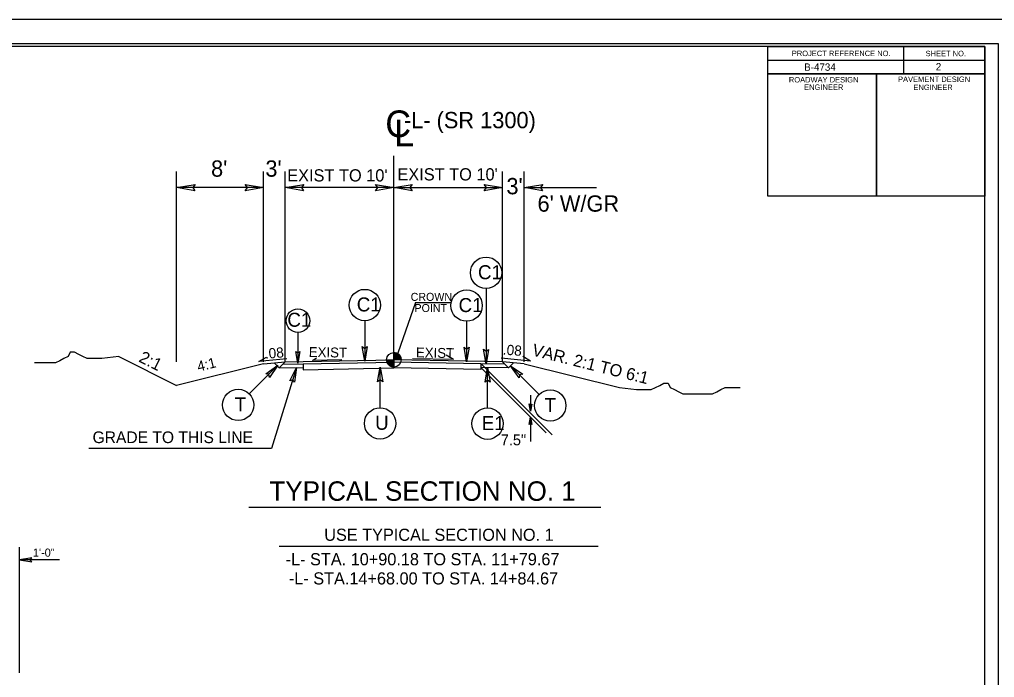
# Model space of a CAD drawing. Extents: x 1818040 to 1825768, y 638918 to 648046.
# Drawn here: x 1821171 to 1822069, y 645878 to 646483 of the extents above; entities that cross this region are included whole.
import ezdxf

# ---------------------------------------------------------------- set-up
doc = ezdxf.new("R2010")
doc.units = 0
for name, color, linetype in [('Default', 7, 'Continuous'), ('Old_Level_1', 7, 'Continuous'), ('Prop Dimension', 7, 'Continuous'), ('Prop Dimension Text', 7, 'Continuous'), ('Sheet Data Field CELL', 7, 'Continuous'), ('Sheet Plot Border Inside CELL', 7, 'Continuous'), ('Sheet Plot Border Outside CELL', 7, 'Continuous'), ('Sheet Typical CELL', 7, 'Continuous'), ('Typical Grade Point Symbol CELL', 7, 'Continuous'), ('Typical ID Circle CELL', 7, 'Continuous'), ('Typical Pavement Slope CELL', 7, 'Continuous'), ('Typical Pavement Slope Information CELL', 7, 'Continuous'), ('Typical Shoulder Slope CELL', 7, 'Continuous'), ('Typical Slope Point Local CELL', 7, 'Continuous'), ('Typical Terminator CELL', 7, 'Continuous'), ('Typical Text Centerline CELL', 7, 'Continuous'), ('Typical Text General CELL', 7, 'Continuous'), ('Typical Text Grade Point CELL', 7, 'Continuous'), ('Typical Text ID Circle CELL', 7, 'Continuous'), ('Typical Text Label CELL', 7, 'Continuous')]:
    doc.layers.add(name, color=color, linetype=linetype)

msp = doc.modelspace()

# ---------------------------------------------------------------- linework, layer by layer
at = {"layer": 'Default'}
for p, q in [((1821440.94, 646169.55), (1821444.36, 646172.12)), ((1821467.78, 646170.19), (1821440.94, 646169.55)), ((1821171.15, 645881.99), (1821171.15, 645997.66)), ((1821207.77, 645986.11), (1821171.15, 645986.11))]:
    msp.add_line(p, q, dxfattribs=at)
at = {"layer": 'Old_Level_1'}
for p, q in [((1821315.74, 646168.26), (1821315.74, 646343.71)), ((1821425.94, 646163.07), (1821403.15, 646088.52)), ((1821410.22, 646162.74), (1821405.54, 646167.41)), ((1821415.74, 646168.26), (1821410.22, 646162.74)), ((1821410.22, 646162.74), (1821432.22, 646163.18)), ((1821413.62, 646166.14), (1821432.22, 646166.51)), ((1821432.22, 646166.51), (1821515.74, 646168.18)), ((1821432.22, 646166.51), (1821432.22, 646161.09)), ((1821432.22, 646161.09), (1821515.74, 646162.76)), ((1821595.7, 646166.58), (1821515.74, 646168.18)), ((1821595.7, 646161.16), (1821515.74, 646162.76)), ((1821617.87, 646166.14), (1821595.7, 646166.58)), ((1821595.7, 646166.58), (1821595.7, 646161.16)), ((1821595.7, 646163.25), (1821655.83, 646103.12)), ((1821621.27, 646162.74), (1821595.7, 646163.25)), ((1821596.25, 646166.25), (1821661.41, 646101.09)), ((1821615.74, 646168.26), (1821621.27, 646162.74)), ((1821621.27, 646162.74), (1821625.95, 646167.41)), ((1821641.47, 646137.69), (1821641.47, 646122.85)), ((1821641.47, 646117.35), (1821641.47, 646095.04)), ((1821403.15, 646088.52), (1821234.74, 646088.52))]:
    msp.add_line(p, q, dxfattribs=at)
at = {"layer": 'Prop Dimension'}
for p, q in [((1821515.74, 646170.26), (1821515.74, 646357.92)), ((1821395.74, 646168.26), (1821395.74, 646343.71)), ((1821415.74, 646168.26), (1821415.74, 646343.71)), ((1821615.74, 646168.26), (1821615.74, 646343.71)), ((1821635.74, 646168.26), (1821635.74, 646343.71)), ((1821395.74, 646328.71), (1821315.74, 646328.71)), ((1821515.74, 646328.71), (1821415.74, 646328.71)), ((1821515.74, 646328.71), (1821615.74, 646328.71)), ((1821635.74, 646328.71), (1821702.28, 646328.71))]:
    msp.add_line(p, q, dxfattribs=at)
at = {"layer": 'Sheet Plot Border Inside CELL'}
msp.add_lwpolyline([(1822072.43, 646461.05), (1820405.93, 646461.05), (1820405.93, 645405.95), (1822072.43, 645405.95)], close=True, dxfattribs=at)
at = {"layer": 'Sheet Plot Border Outside CELL'}
msp.add_lwpolyline([(1822076.93, 646483.5), (1820392.93, 646483.5), (1820392.93, 645383.5), (1822076.93, 645383.5)], close=True, dxfattribs=at)
at = {"layer": 'Sheet Typical CELL'}
for p, q in [((1822076.93, 646483.5), (1820392.93, 646483.5)), ((1821984.93, 646458.45), (1821984.93, 646433.45)), ((1821859.88, 646445.95), (1822059.93, 646445.95)), ((1821959.93, 646433.45), (1821959.93, 646321))]:
    msp.add_line(p, q, dxfattribs=at)
for points in [[(1822059.93, 646458.5), (1820559.93, 646458.5), (1820559.93, 645408.5), (1822059.93, 645408.5)], [(1821859.88, 646458.5), (1822059.93, 646458.5), (1822059.93, 646433.45), (1821859.88, 646433.45)], [(1821859.88, 646433.45), (1821959.93, 646433.45), (1821959.93, 646320.95), (1821859.88, 646320.95)], [(1821959.93, 646433.45), (1822059.93, 646433.45), (1822059.93, 646320.95), (1821959.93, 646320.95)]]:
    msp.add_lwpolyline(points, close=True, dxfattribs=at)
at = {"layer": 'Typical Grade Point Symbol CELL'}
for p, q in [((1821515.74, 646170.26), (1821515.74, 646176.98)), ((1821509.03, 646170.26), (1821515.74, 646170.26)), ((1821515.73, 646163.55), (1821515.74, 646170.26)), ((1821515.74, 646170.26), (1821515.73, 646163.55)), ((1821522.46, 646170.26), (1821515.74, 646170.26))]:
    msp.add_line(p, q, dxfattribs=at)
for points in [[(1821515.8, 646176.98), (1821515.8, 646176.98), (1821515.8, 646170.26)], [(1821515.94, 646176.98), (1821515.94, 646170.26)], [(1821516.07, 646176.96), (1821516.07, 646170.26)], [(1821516.21, 646176.96), (1821516.21, 646170.26)], [(1821516.34, 646176.95), (1821516.34, 646170.26)], [(1821516.48, 646176.93), (1821516.48, 646170.26)], [(1821516.61, 646176.92), (1821516.61, 646170.26)], [(1821516.74, 646176.9), (1821516.74, 646170.26)], [(1821516.88, 646176.89), (1821516.88, 646170.26)], [(1821517.01, 646176.86), (1821517.01, 646170.26)], [(1821517.15, 646176.83), (1821517.15, 646170.26)], [(1821517.28, 646176.8), (1821517.28, 646170.26)], [(1821517.42, 646176.77), (1821517.42, 646170.26)], [(1821517.55, 646176.73), (1821517.55, 646170.26)], [(1821517.68, 646176.69), (1821517.68, 646170.26)], [(1821517.82, 646176.65), (1821517.82, 646170.26)], [(1821517.95, 646176.61), (1821517.95, 646170.26)], [(1821518.09, 646176.56), (1821518.09, 646170.26)], [(1821518.22, 646176.5), (1821518.22, 646170.26)], [(1821518.36, 646176.44), (1821518.36, 646170.26)], [(1821518.49, 646176.38), (1821518.49, 646170.26)], [(1821518.62, 646176.32), (1821518.62, 646170.26)], [(1821518.76, 646176.26), (1821518.76, 646170.26)], [(1821518.89, 646176.19), (1821518.89, 646170.26)], [(1821519.03, 646176.11), (1821519.03, 646170.26)], [(1821519.16, 646176.04), (1821519.16, 646170.26)], [(1821519.3, 646175.96), (1821519.3, 646170.26)], [(1821519.43, 646175.87), (1821519.43, 646170.26)], [(1821519.56, 646175.78), (1821519.56, 646170.26)], [(1821519.7, 646175.68), (1821519.7, 646170.26)], [(1821519.83, 646175.59), (1821519.83, 646170.26)], [(1821519.97, 646175.49), (1821519.97, 646170.26)], [(1821520.1, 646175.37), (1821520.1, 646170.26)], [(1821520.23, 646175.25), (1821520.23, 646170.26)], [(1821520.37, 646175.13), (1821520.37, 646170.26)], [(1821520.5, 646174.99), (1821520.5, 646170.26)], [(1821520.64, 646174.86), (1821520.64, 646170.26)], [(1821520.77, 646174.71), (1821520.77, 646170.26)], [(1821520.91, 646174.55), (1821520.91, 646170.26)], [(1821521.04, 646174.38), (1821521.04, 646170.26)], [(1821521.18, 646174.2), (1821521.18, 646170.26)], [(1821521.31, 646174.01), (1821521.31, 646170.26)], [(1821521.44, 646173.8), (1821521.44, 646170.26)], [(1821521.58, 646173.58), (1821521.58, 646170.26)], [(1821521.71, 646173.34), (1821521.71, 646170.26)], [(1821521.85, 646173.05), (1821521.85, 646170.26)], [(1821521.98, 646172.74), (1821521.98, 646170.26)], [(1821522.11, 646172.37), (1821522.11, 646170.26)], [(1821522.25, 646171.91), (1821522.25, 646170.26)], [(1821522.38, 646171.22), (1821522.38, 646170.26)], [(1821509.06, 646170.26), (1821509.06, 646169.53)], [(1821509.19, 646170.26), (1821509.19, 646168.74)], [(1821509.33, 646170.26), (1821509.33, 646168.27)], [(1821509.46, 646170.26), (1821509.46, 646167.86)], [(1821509.6, 646170.26), (1821509.6, 646167.55)], [(1821509.73, 646170.26), (1821509.73, 646167.27)], [(1821509.87, 646170.26), (1821509.87, 646167.01)], [(1821510, 646170.26), (1821510, 646166.77)], [(1821510.13, 646170.26), (1821510.13, 646166.57)], [(1821510.27, 646170.26), (1821510.27, 646166.37)], [(1821510.4, 646170.26), (1821510.4, 646166.19)], [(1821510.54, 646170.26), (1821510.54, 646166.03)], [(1821510.67, 646170.26), (1821510.67, 646165.86)], [(1821510.81, 646170.26), (1821510.81, 646165.71)], [(1821510.94, 646170.26), (1821510.94, 646165.57)], [(1821511.07, 646170.26), (1821511.07, 646165.43)], [(1821511.21, 646170.26), (1821511.21, 646165.31)], [(1821511.34, 646170.26), (1821511.34, 646165.19)], [(1821511.48, 646170.26), (1821511.48, 646165.07)], [(1821511.61, 646170.26), (1821511.61, 646164.97)], [(1821511.75, 646170.26), (1821511.75, 646164.86)], [(1821511.88, 646170.26), (1821511.88, 646164.77)], [(1821512.01, 646170.26), (1821512.01, 646164.69)], [(1821512.15, 646170.26), (1821512.15, 646164.6)], [(1821512.28, 646170.26), (1821512.28, 646164.51)], [(1821512.42, 646170.26), (1821512.42, 646164.43)], [(1821512.55, 646170.26), (1821512.55, 646164.36)], [(1821512.69, 646170.26), (1821512.69, 646164.28)], [(1821512.82, 646170.26), (1821512.82, 646164.22)], [(1821512.95, 646170.26), (1821512.95, 646164.16)], [(1821513.09, 646170.26), (1821513.09, 646164.1)], [(1821513.22, 646170.26), (1821513.22, 646164.04)], [(1821513.36, 646170.26), (1821513.36, 646163.98)], [(1821513.49, 646170.26), (1821513.49, 646163.94)], [(1821513.63, 646170.26), (1821513.63, 646163.89)], [(1821513.76, 646170.26), (1821513.76, 646163.85)], [(1821513.89, 646170.26), (1821513.89, 646163.82)], [(1821514.03, 646170.26), (1821514.03, 646163.78)], [(1821514.16, 646170.26), (1821514.16, 646163.75)], [(1821514.3, 646170.26), (1821514.3, 646163.71)], [(1821514.43, 646170.26), (1821514.43, 646163.69)], [(1821514.57, 646170.26), (1821514.57, 646163.66)], [(1821514.7, 646170.26), (1821514.7, 646163.64)], [(1821514.83, 646170.26), (1821514.83, 646163.61)], [(1821514.97, 646170.26), (1821514.97, 646163.6)], [(1821515.1, 646170.26), (1821515.1, 646163.58)], [(1821515.24, 646170.26), (1821515.24, 646163.57)], [(1821515.37, 646170.26), (1821515.37, 646163.57)], [(1821515.51, 646170.26), (1821515.51, 646163.55)], [(1821515.64, 646170.26), (1821515.64, 646163.55), (1821515.64, 646163.55)]]:
    msp.add_lwpolyline(points, dxfattribs=at)
msp.add_circle((1821515.74, 646170.27), 6.71, dxfattribs=at)
for start, end in [(359.99048, 89.99048), (179.99048, 269.99048)]:
    msp.add_arc((1821515.74, 646170.27), 6.71, start, end, dxfattribs=at)
at = {"layer": 'Typical ID Circle CELL'}
for p, q in [((1821600.56, 646235.91), (1821600.56, 646166.48)), ((1821488.98, 646206.23), (1821488.98, 646168.95)), ((1821582.71, 646205.65), (1821582.71, 646168.37)), ((1821427.43, 646195.36), (1821427.43, 646167.25)), ((1821382.58, 646138.85), (1821408.96, 646165.21)), ((1821649.53, 646138.31), (1821623.16, 646164.67)), ((1821503.04, 646126.11), (1821503.04, 646160.56)), ((1821601.94, 646125.84), (1821601.94, 646160.29))]:
    msp.add_line(p, q, dxfattribs=at)
for centre, radius in [((1821600.56, 646250.33), 14.43), ((1821488.98, 646220.65), 14.43), ((1821582.71, 646220.07), 14.43), ((1821427.43, 646206.23), 10.88), ((1821372.39, 646128.65), 14.43), ((1821659.72, 646128.11), 14.43), ((1821503.04, 646111.68), 14.43), ((1821601.94, 646111.42), 14.43)]:
    msp.add_circle(centre, radius, dxfattribs=at)
at = {"layer": 'Typical Pavement Slope CELL'}
for p in [(1821415.74, 646168.26), (1821615.74, 646168.26)]:
    msp.add_line(p, (1821515.74, 646170.26), dxfattribs=at)
at = {"layer": 'Typical Pavement Slope Information CELL'}
for p, q in [((1821391.42, 646168.57), (1821398.31, 646172.73)), ((1821417.25, 646171.06), (1821391.42, 646168.57)), ((1821570.72, 646170.42), (1821532.75, 646171.18)), ((1821570.72, 646170.42), (1821563.97, 646174.5)), ((1821641.37, 646169.04), (1821614.49, 646171.64)), ((1821641.37, 646169.04), (1821634.47, 646173.21))]:
    msp.add_line(p, q, dxfattribs=at)
at = {"layer": 'Typical Shoulder Slope CELL'}
for p, q in [((1821395.74, 646166.6), (1821415.74, 646168.26)), ((1821635.74, 646166.6), (1821615.74, 646168.26))]:
    msp.add_line(p, q, dxfattribs=at)
at = {"layer": 'Typical Slope Point Local CELL'}
for p, q in [((1821262.54, 646173.2), (1821315.74, 646146.6)), ((1821395.74, 646166.6), (1821315.74, 646146.6)), ((1821635.74, 646166.6), (1821723.49, 646144.66))]:
    msp.add_line(p, q, dxfattribs=at)
for points in [[(1821262.54, 646173.2), (1821246.98, 646171.26), (1821243.09, 646171.26), (1821237.25, 646171.26), (1821233.36, 646171.26), (1821229.47, 646173.2), (1821225.58, 646175.15), (1821221.69, 646177.1), (1821217.8, 646177.1), (1821215.85, 646173.2), (1821211.96, 646171.26), (1821208.07, 646169.31), (1821204.18, 646167.37), (1821200.29, 646167.37), (1821196.4, 646167.37), (1821192.51, 646167.37), (1821188.62, 646167.37), (1821184.73, 646167.37)], [(1821723.49, 646144.66), (1821739.05, 646142.72), (1821742.94, 646142.72), (1821748.79, 646142.72), (1821752.68, 646142.72), (1821756.57, 646144.66), (1821760.46, 646146.61), (1821764.35, 646148.57), (1821768.24, 646148.57), (1821770.19, 646144.66), (1821774.08, 646142.72), (1821777.97, 646140.77), (1821781.86, 646138.83), (1821785.75, 646138.83), (1821789.64, 646138.83), (1821793.53, 646138.83), (1821797.42, 646138.83), (1821801.31, 646138.83), (1821805.2, 646138.83), (1821809.09, 646138.83), (1821812.98, 646140.77), (1821816.87, 646142.72), (1821820.76, 646144.66), (1821826.6, 646144.66), (1821830.49, 646144.66), (1821834.38, 646144.66)]]:
    msp.add_lwpolyline(points, dxfattribs=at)
at = {"layer": 'Typical Terminator CELL'}
for points in [[(1821332.62, 646325.81), (1821315.74, 646328.71), (1821332.71, 646331.71), (1821330.56, 646328.71)], [(1821378.87, 646331.62), (1821395.74, 646328.71), (1821378.78, 646325.71), (1821380.93, 646328.71)], [(1821432.62, 646325.81), (1821415.74, 646328.71), (1821432.71, 646331.71), (1821430.56, 646328.71)], [(1821498.87, 646331.62), (1821515.74, 646328.71), (1821498.78, 646325.71), (1821500.93, 646328.71)], [(1821532.62, 646325.81), (1821515.74, 646328.71), (1821532.71, 646331.71), (1821530.56, 646328.71)], [(1821598.87, 646331.62), (1821615.74, 646328.71), (1821598.78, 646325.71), (1821600.93, 646328.71)], [(1821652.62, 646325.81), (1821635.74, 646328.71), (1821652.71, 646331.71), (1821650.56, 646328.71)], [(1821491.28, 646182.31), (1821488.98, 646168.95), (1821486.6, 646182.38), (1821488.98, 646180.68)], [(1821585.01, 646181.73), (1821582.71, 646168.37), (1821580.33, 646181.8), (1821582.71, 646180.1)], [(1821602.87, 646179.84), (1821600.56, 646166.48), (1821598.19, 646179.92), (1821600.56, 646178.21)], [(1821429.25, 646177.79), (1821427.43, 646167.25), (1821425.56, 646177.85), (1821427.43, 646176.5)], [(1821397.88, 646157.39), (1821408.96, 646165.21), (1821401.14, 646154.03), (1821400.66, 646156.92)], [(1821419.89, 646150.93), (1821425.95, 646163.05), (1821424.34, 646149.51), (1821422.56, 646151.83)], [(1821500.74, 646150.03), (1821503.04, 646163.39), (1821505.42, 646149.96), (1821503.04, 646151.66)], [(1821599.64, 646149.77), (1821601.94, 646163.12), (1821604.32, 646149.69), (1821601.94, 646151.4)], [(1821630.98, 646153.6), (1821623.16, 646164.67), (1821634.34, 646156.86), (1821631.45, 646156.38)], [(1821642.68, 646129.52), (1821641.47, 646122.85), (1821640.34, 646129.58), (1821641.52, 646128.72)], [(1821640.35, 646110.67), (1821641.47, 646117.35), (1821642.68, 646110.64), (1821641.49, 646111.49)], [(1821182.39, 645988.05), (1821171.15, 645986.11), (1821182.46, 645984.11), (1821181.02, 645986.11)]]:
    msp.add_lwpolyline(points, close=True, dxfattribs=at)
at = {"layer": 'Typical Text Grade Point CELL'}
for q in [(1821517.28, 646170.26), (1821567.56, 646223.04)]:
    msp.add_line((1821535.61, 646223.04), q, dxfattribs=at)
at = {"layer": 'Typical Text Label CELL'}
for p, q in [((1821382.31, 646034.41), (1821706.37, 646034.41)), ((1821410.08, 645998.66), (1821703.93, 645998.66))]:
    msp.add_line(p, q, dxfattribs=at)

# ---------------------------------------------------------------- texts
at = {"layer": 'Prop Dimension Text'}
for s, height, p in [('-L- (SR 1300)', 15, (1821524.94, 646383.37)), ("8'", 15, (1821347.43, 646338.78)), ("3'", 15, (1821397.43, 646338.78)), ("EXIST TO 10'", 11.25, (1821417.54, 646334.37)), ("EXIST TO 10'", 11.25, (1821518.99, 646335.33)), ("3'", 15, (1821619.34, 646322.58)), ("6' W/GR", 15, (1821647.96, 646306.57)), ('7.5"', 10, (1821614.16, 646091.51))]:
    msp.add_text(s, height=height, dxfattribs=at).set_placement(p)
at = {"layer": 'Sheet Data Field CELL'}
for s, height, p in [('B-4734   ', 6.75, (1821893.45, 646436.3)), (' 2 ', 6.75, (1822012.14, 646436.6)), ('1\'-0"', 7.5, (1821183.43, 645988.94))]:
    msp.add_text(s, height=height, dxfattribs=at).set_placement(p)
at = {"layer": 'Sheet Typical CELL'}
for s, height, p in [('PROJECT REFERENCE NO.', 5.0001, (1821882.08, 646449.8)), ('SHEET NO.', 5, (1822005.23, 646449.7)), ('PAVEMENT DESIGN', 5.0001, (1821979.88, 646426)), ('ROADWAY DESIGN', 5.0001, (1821879.38, 646425.55)), ('ENGINEER', 5, (1821893.43, 646418.7)), ('ENGINEER', 5, (1821994.08, 646418.55))]:
    msp.add_text(s, height=height, dxfattribs=at).set_placement(p)
at = {"layer": 'Typical Pavement Slope Information CELL'}
for s, p in [('EXIST', (1821437.31, 646172.87)), ('EXIST ', (1821535.93, 646172.47))]:
    msp.add_text(s, height=9.107, rotation=358.85426, dxfattribs=at).set_placement(p)
at = {"layer": 'Typical Slope Point Local CELL'}
for s, rotation, p in [('.08', 4.76147, (1821397.34, 646171.07)), ('.08', 355.23853, (1821615.75, 646175.15)), ('4:1', 14.03624, (1821335.9, 646159.29))]:
    msp.add_text(s, height=9.373, rotation=rotation, dxfattribs=at).set_placement(p)
at = {"layer": 'Typical Text Centerline CELL'}
msp.add_text('C', height=24.6, dxfattribs=at).set_placement((1821507.81, 646375.18))
msp.add_text('L', height=24.62, rotation=359.9469, dxfattribs=at).set_placement((1821515.99, 646366.78))
at = {"layer": 'Typical Text General CELL'}
for s, height, rotation, p in [('VAR. 2:1 TO 6:1', 11.1896, 345.96376, (1821642.18, 646174.31)), ('2:1 ', 11.19, 333.43495, (1821280.07, 646168.86))]:
    msp.add_text(s, height=height, rotation=rotation, dxfattribs=at).set_placement(p)
msp.add_text('GRADE TO THIS LINE', height=10.742, dxfattribs=at).set_placement((1821238.32, 646093.52))
at = {"layer": 'Typical Text Grade Point CELL'}
for s, height, p in [('CROWN', 7.34, (1821531.15, 646224.49)), ('POINT', 7.34, (1821534.69, 646214.19)), ('-L- STA. 10+90.18 TO STA. 11+79.67', 11.1896, (1821416.12, 645981.03)), ('-L- STA.14+68.00 TO STA. 14+84.67', 11.1896, (1821419.05, 645963.37))]:
    msp.add_text(s, height=height, dxfattribs=at).set_placement(p)
at = {"layer": 'Typical Text ID Circle CELL'}
for s, height, p in [('C1', 12.912, (1821593.16, 646244.39)), ('C1', 12.912, (1821481.57, 646214.71)), ('C1', 12.912, (1821575.3, 646214.13)), ('C1', 12.912, (1821417.69, 646200.62)), ('T', 12.91, (1821369.18, 646122.7)), ('T', 12.91, (1821654.44, 646122.17)), ('U', 12.91, (1821498.48, 646105.74)), ('E1', 12.912, (1821596.62, 646105.48))]:
    msp.add_text(s, height=height, dxfattribs=at).set_placement(p)
at = {"layer": 'Typical Text Label CELL'}
for s, height, p in [('TYPICAL SECTION NO. 1  ', 17.9034, (1821401.12, 646040.41)), ('USE TYPICAL SECTION NO. 1', 11.1896, (1821451.62, 646003.55))]:
    msp.add_text(s, height=height, dxfattribs=at).set_placement(p)

doc.saveas('drawing.dxf')
